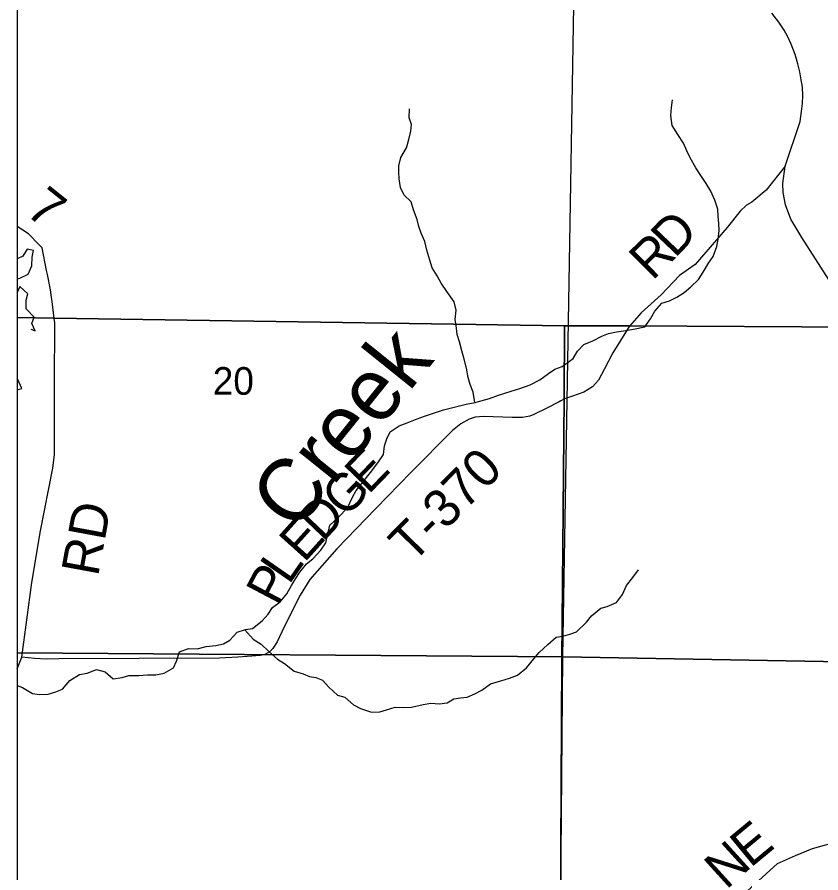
# Model space of a CAD drawing. Extents: x -3.6 to 34, y 0 to 32.8.
# Drawn here: x -3.63 to -2.413, y 29.806 to 31.101 of the extents above; entities that cross this region are included whole.
import ezdxf

# ---------------------------------------------------------------- set-up
doc = ezdxf.new("R2010")
doc.units = 0
for name, color, linetype in [('GM_X_Corporation', 7, 'Continuous'), ('GM_X_Major_River', 7, 'Continuous'), ('GM_X_Major_River_Text', 7, 'Continuous'), ('GM_X_Minor_Lake', 7, 'Continuous'), ('GM_X_Minor_River', 7, 'Continuous'), ('GM_X_Section_Text', 7, 'Continuous'), ('GM_X_State_Route', 7, 'Continuous'), ('GM_X_Township_Road', 7, 'Continuous'), ('GM_X_Township_Road_Text', 7, 'Continuous'), ('SH_Data', 7, 'Continuous')]:
    doc.layers.add(name, color=color, linetype=linetype)

msp = doc.modelspace()

# ---------------------------------------------------------------- linework, layer by layer
at = {"layer": 'GM_X_Corporation'}
for points in [[(3.1705, 28.9337), (3.1705, 32.8429), (-3.6295, 32.8429), (-3.6295, 26.0429), (2.3706, 26.0429), (2.3712, 26.0804), (2.3716, 26.1248), (2.3732, 26.2253), (2.3789, 26.6097), (2.3911, 27.5117), (2.3952, 27.9336), (2.3997, 28.282), (2.4082, 28.9473), (2.5416, 28.945), (2.5837, 28.9442), (2.8343, 28.9397)], [(3.1705, 30.458), (3.1705, 32.8429), (-3.6295, 32.8429), (-3.6295, 30.6462), (-3.5736, 30.6453), (-2.8007, 30.6338), (-2.7027, 30.634), (-2.3541, 30.6318), (-0.5034, 30.5954), (-0.453, 30.5952), (-0.398, 30.5946), (0.2583, 30.5905), (0.2578, 30.5133), (0.3556, 30.5115), (0.4055, 30.5105), (1.2437, 30.4948), (1.7819, 30.4857), (3.0419, 30.4594)], [(-3.6295, 31.1685), (-3.6295, 30.1386), (-2.8032, 30.1329), (-2.786, 31.1483)], [(-1.7722, 31.1326), (-1.7886, 30.1145), (-2.8032, 30.1329), (-2.786, 31.1483)], [(-3.6295, 30.6462), (-3.6295, 26.0429), (-2.8635, 26.0429), (-2.8499, 26.4099), (-2.8426, 27.1), (-2.8208, 28.0589), (-2.813, 28.9119), (-2.8073, 29.6484), (-2.8047, 30.129), (-2.8012, 30.524), (-2.8007, 30.6338), (-3.5736, 30.6453)], [(-3.6295, 30.1386), (-3.6295, 29.124), (-2.8121, 29.1143), (-2.8032, 30.1329)], [(-1.7886, 30.1145), (-1.8059, 29.1018), (-2.8121, 29.1143), (-2.8032, 30.1329)]]:
    msp.add_lwpolyline(points, close=True, dxfattribs=at)
msp.add_lwpolyline([(-0.398, 30.5946), (-0.453, 30.5952), (-0.5034, 30.5954), (-2.3541, 30.6318), (-2.7027, 30.634), (-2.8007, 30.6338), (-2.8012, 30.524), (-2.8047, 30.129), (-2.8073, 29.6484), (-2.813, 28.9119), (-2.8208, 28.0589), (-2.8426, 27.1), (-2.8499, 26.4099), (-2.8635, 26.0429), (2.3706, 26.0429)], dxfattribs=at)
at = {"layer": 'GM_X_Major_River'}
for points in [[(-2.8814, 30.5347), (-2.8682, 30.5388), (-2.8528, 30.5444), (-2.8382, 30.552), (-2.8251, 30.5617), (-2.8154, 30.568), (-2.8041, 30.5724), (-2.7877, 30.5841), (-2.7811, 30.5952), (-2.7715, 30.6057), (-2.758, 30.6113), (-2.7441, 30.618), (-2.734, 30.622), (-2.7219, 30.6245), (-2.7079, 30.6267), (-2.6962, 30.6289), (-2.6792, 30.6323), (-2.6708, 30.6442), (-2.6642, 30.6561), (-2.6535, 30.6681), (-2.6418, 30.6717), (-2.6306, 30.6769), (-2.6197, 30.6843), (-2.6093, 30.6929), (-2.5978, 30.7037), (-2.5908, 30.7149), (-2.5828, 30.7287), (-2.5758, 30.7387), (-2.5701, 30.7536), (-2.5684, 30.765), (-2.5668, 30.7783), (-2.5674, 30.7889), (-2.568, 30.7999), (-2.5686, 30.8105), (-2.5731, 30.8241), (-2.5791, 30.8376), (-2.5861, 30.8492), (-2.5943, 30.8615), (-2.6022, 30.8727), (-2.6108, 30.8881), (-2.6156, 30.8986), (-2.6208, 30.9102), (-2.6294, 30.9233), (-2.6376, 30.9372), (-2.6398, 30.9519), (-2.639, 30.9644), (-2.6373, 30.9759)], [(-3.6295, 30.0894), (-3.6216, 30.0863), (-3.6062, 30.0771), (-3.5956, 30.0758), (-3.5827, 30.0761), (-3.5707, 30.0798), (-3.5609, 30.0837), (-3.5498, 30.0969), (-3.5349, 30.1059), (-3.5235, 30.108), (-3.5093, 30.1136), (-3.4963, 30.1101), (-3.484, 30.0994), (-3.4704, 30.1012), (-3.4606, 30.1044), (-3.4454, 30.1047), (-3.4322, 30.1054), (-3.4193, 30.1057), (-3.4069, 30.1082), (-3.393, 30.1161), (-3.3883, 30.126), (-3.3837, 30.1405), (-3.3701, 30.1454), (-3.3569, 30.1449), (-3.3433, 30.1482), (-3.3289, 30.15), (-3.3173, 30.1522), (-3.3075, 30.158), (-3.2964, 30.17), (-3.2836, 30.1741), (-3.2734, 30.1758), (-3.2585, 30.1871), (-3.2496, 30.1972), (-3.243, 30.2075), (-3.2311, 30.2158), (-3.2211, 30.2281), (-3.2142, 30.2408), (-3.2083, 30.2507), (-3.2017, 30.2607), (-3.1914, 30.2735), (-3.1817, 30.2812), (-3.1699, 30.294), (-3.1621, 30.3052), (-3.1559, 30.3318), (-3.1433, 30.3435), (-3.1292, 30.3585), (-3.1216, 30.3746), (-3.1161, 30.3846), (-3.1061, 30.3969), (-3.0947, 30.412), (-3.0836, 30.4262), (-3.0748, 30.4389), (-3.0732, 30.4522), (-3.0696, 30.4629), (-3.0649, 30.4733), (-3.0511, 30.4826), (-3.0391, 30.4867), (-3.0237, 30.4931), (-3.0128, 30.4971), (-3.0008, 30.5011), (-2.9838, 30.5068), (-2.9499, 30.5151), (-2.9363, 30.5177), (-2.9254, 30.5209), (-2.9145, 30.5238), (-2.9009, 30.5286), (-2.8814, 30.5347)]]:
    msp.add_lwpolyline(points, dxfattribs=at)
at = {"layer": 'GM_X_Minor_Lake'}
msp.add_line((-3.6254, 30.6933), (-3.6295, 30.684), dxfattribs=at)
for points in [[(-3.6295, 30.7049), (-3.6252, 30.7058), (-3.6128, 30.7121), (-3.6074, 30.7247), (-3.6068, 30.7376), (-3.6047, 30.7479), (-3.6142, 30.7496), (-3.6209, 30.7393), (-3.6295, 30.7352)], [(-3.6089, 30.6286), (-3.6023, 30.6262), (-3.607, 30.6371), (-3.6038, 30.6471), (-3.6157, 30.6594), (-3.6156, 30.6726), (-3.6134, 30.6821), (-3.6254, 30.6933)], [(-3.6295, 30.5369), (-3.6223, 30.5391), (-3.629, 30.5534), (-3.6295, 30.5546)]]:
    msp.add_lwpolyline(points, dxfattribs=at)
at = {"layer": 'GM_X_Minor_River'}
for points in [[(-2.9367, 30.5176), (-2.9393, 30.5332), (-2.9437, 30.5449), (-2.9465, 30.5555), (-2.949, 30.5698), (-2.9531, 30.5853), (-2.9563, 30.5959), (-2.9596, 30.6094), (-2.9632, 30.6204), (-2.9645, 30.6302), (-2.9662, 30.6431), (-2.9649, 30.6575), (-2.9678, 30.6703), (-2.9791, 30.6857), (-2.9876, 30.6984), (-2.9935, 30.7093), (-3.0009, 30.7217), (-3.0049, 30.7334), (-3.0093, 30.7481), (-3.0125, 30.7613), (-3.0177, 30.7741), (-3.0213, 30.7843), (-3.0241, 30.7948), (-3.0293, 30.8095), (-3.0329, 30.8216), (-3.0437, 30.8317), (-3.0492, 30.8433), (-3.0509, 30.8565), (-3.0515, 30.8664), (-3.0516, 30.8759), (-3.0488, 30.8884), (-3.04, 30.903), (-3.0364, 30.9159), (-3.0336, 30.9285), (-3.0323, 30.9387), (-3.0362, 30.9485), (-3.0357, 30.9622)], [(-3.285, 30.1737), (-3.2724, 30.1595), (-3.2602, 30.1521), (-3.2483, 30.141), (-3.2352, 30.1291), (-3.2249, 30.1228), (-3.2103, 30.1109), (-3.1966, 30.107), (-3.1867, 30.103), (-3.1772, 30.1016), (-3.1673, 30.0976), (-3.1576, 30.0868), (-3.1445, 30.0749), (-3.1335, 30.0717), (-3.1204, 30.0601), (-3.1097, 30.0543), (-3.093, 30.0492), (-3.0805, 30.0494), (-3.0703, 30.0526), (-3.0572, 30.0567), (-3.0443, 30.0561), (-3.0322, 30.0563), (-3.0148, 30.0604), (-3.0031, 30.0625), (-2.9902, 30.0616), (-2.9785, 30.0633), (-2.9684, 30.0692), (-2.9582, 30.0705), (-2.9484, 30.0718), (-2.9364, 30.0765), (-2.9259, 30.0824), (-2.9128, 30.0921), (-2.8974, 30.0965), (-2.8842, 30.1005), (-2.8721, 30.1049), (-2.8583, 30.1161), (-2.8472, 30.1296), (-2.839, 30.1392), (-2.826, 30.1512), (-2.8133, 30.1624), (-2.8035, 30.1641), (-2.7926, 30.1669), (-2.7828, 30.1705), (-2.7675, 30.1852), (-2.7597, 30.1948), (-2.7459, 30.2064), (-2.7361, 30.2088), (-2.7219, 30.2148), (-2.713, 30.227), (-2.7068, 30.2408), (-2.6971, 30.2527), (-2.689, 30.2646)]]:
    msp.add_lwpolyline(points, dxfattribs=at)
at = {"layer": 'GM_X_State_Route'}
for points in [[(-2.4669, 30.8754), (-2.444, 30.9431), (-2.4421, 30.958), (-2.4404, 30.9704), (-2.4398, 30.9822), (-2.4407, 30.995), (-2.4423, 31.0061), (-2.4444, 31.0182), (-2.4475, 31.0301), (-2.4514, 31.0445), (-2.4575, 31.0601), (-2.4631, 31.0722), (-2.4684, 31.0815), (-2.4764, 31.0936), (-2.4869, 31.1069)], [(-2.3713, 30.6578), (-2.4414, 30.7673), (-2.4581, 30.7951), (-2.4663, 30.8167), (-2.4697, 30.8355), (-2.4704, 30.8494), (-2.4669, 30.8754)]]:
    msp.add_lwpolyline(points, dxfattribs=at)
at = {"layer": 'GM_X_Township_Road'}
for points in [[(-2.4669, 30.8754), (-2.4954, 30.8393), (-2.5171, 30.8207), (-2.5254, 30.8163), (-2.535, 30.8072), (-2.5544, 30.7826), (-2.6031, 30.7267), (-2.6267, 30.7097), (-2.6546, 30.6807), (-2.6849, 30.6533), (-2.7025, 30.6334), (-2.7045, 30.6301)], [(-3.5965, 30.7567), (-3.6122, 30.7729), (-3.6295, 30.7842)], [(-3.5848, 30.7177), (-3.5914, 30.7516), (-3.5922, 30.7523), (-3.5965, 30.7567)], [(-3.5775, 30.6766), (-3.579, 30.688), (-3.5836, 30.7116), (-3.5848, 30.7177)], [(-3.5729, 30.5426), (-3.5729, 30.5457), (-3.5725, 30.6384), (-3.5734, 30.6448), (-3.5767, 30.6704), (-3.5775, 30.6766)], [(-2.7045, 30.6301), (-2.7276, 30.593), (-2.7403, 30.5689), (-2.7492, 30.5513), (-2.7582, 30.5416), (-2.7716, 30.5335), (-2.7889, 30.5275), (-2.801, 30.5235), (-2.8063, 30.5204)], [(-3.6295, 30.1144), (-3.6223, 30.132), (-3.6074, 30.2454), (-3.5939, 30.3234), (-3.5754, 30.4182), (-3.5727, 30.4391), (-3.5729, 30.5342), (-3.5729, 30.5426)], [(-2.8063, 30.5204), (-2.8089, 30.5189), (-2.8275, 30.5091), (-2.8474, 30.4997), (-2.8535, 30.4968), (-2.8645, 30.495), (-2.8799, 30.495), (-2.923, 30.4963), (-2.9359, 30.4954), (-2.9449, 30.4924), (-2.9578, 30.4855), (-2.9704, 30.4751), (-3.0336, 30.4115), (-3.0864, 30.3573), (-3.1453, 30.2962), (-3.1864, 30.2499), (-3.2008, 30.226), (-3.2254, 30.1779), (-3.2359, 30.1556), (-3.2423, 30.1452), (-3.2476, 30.1402), (-3.2545, 30.1361), (-3.2616, 30.1345), (-3.274, 30.1337), (-3.2954, 30.1322), (-3.3232, 30.1305), (-3.5666, 30.1297), (-3.5856, 30.1292), (-3.603, 30.1303), (-3.6223, 30.132)], [(-2.5588, 29.7467), (-2.4785, 29.8197), (-2.4512, 29.832), (-2.4254, 29.8427), (-2.3856, 29.8538)]]:
    msp.add_lwpolyline(points, dxfattribs=at)
at = {"layer": 'SH_Data'}
msp.add_line((-3.6295, 32.8429), (-3.6295, 26.0429), dxfattribs=at)

# ---------------------------------------------------------------- texts
at = {"layer": 'GM_X_Major_River_Text'}
msp.add_text('Creek', height=0.09469, rotation=51.1563, dxfattribs=at).set_placement((-3.2087, 30.3186))
at = {"layer": 'GM_X_Section_Text'}
msp.add_text('20', height=0.04186, rotation=0, dxfattribs=at).set_placement((-3.3333, 30.5294))
at = {"layer": 'GM_X_Township_Road_Text'}
for s, height, rotation, p in [('7', 0.0568, 321.3808, (-3.6187, 30.8039)), ('D', 0.0568, 46.3594, (-2.6337, 30.735)), ('R', 0.0568, 44.8648, (-2.6679, 30.701)), ('E', 0.0568, 45.9243, (-3.0977, 30.3774)), ('T-370', 0.05682, 45.3938, (-3.0312, 30.2725)), ('G', 0.0568, 45.935, (-3.1325, 30.3415)), ('RD', 0.05682, 79.5258, (-3.5071, 30.2531)), ('D', 0.0568, 46.4581, (-3.1669, 30.3054)), ('E', 0.0568, 48.1198, (-3.1949, 30.274)), ('L', 0.0568, 55.2472, (-3.218, 30.2406)), ('P', 0.0568, 62.1631, (-3.235, 30.2082)), ('E', 0.0568, 39.5872, (-2.5195, 29.8124)), ('N', 0.0568, 42.226, (-2.556, 29.7792))]:
    msp.add_text(s, height=height, rotation=rotation, dxfattribs=at).set_placement(p)

doc.saveas('drawing.dxf')
